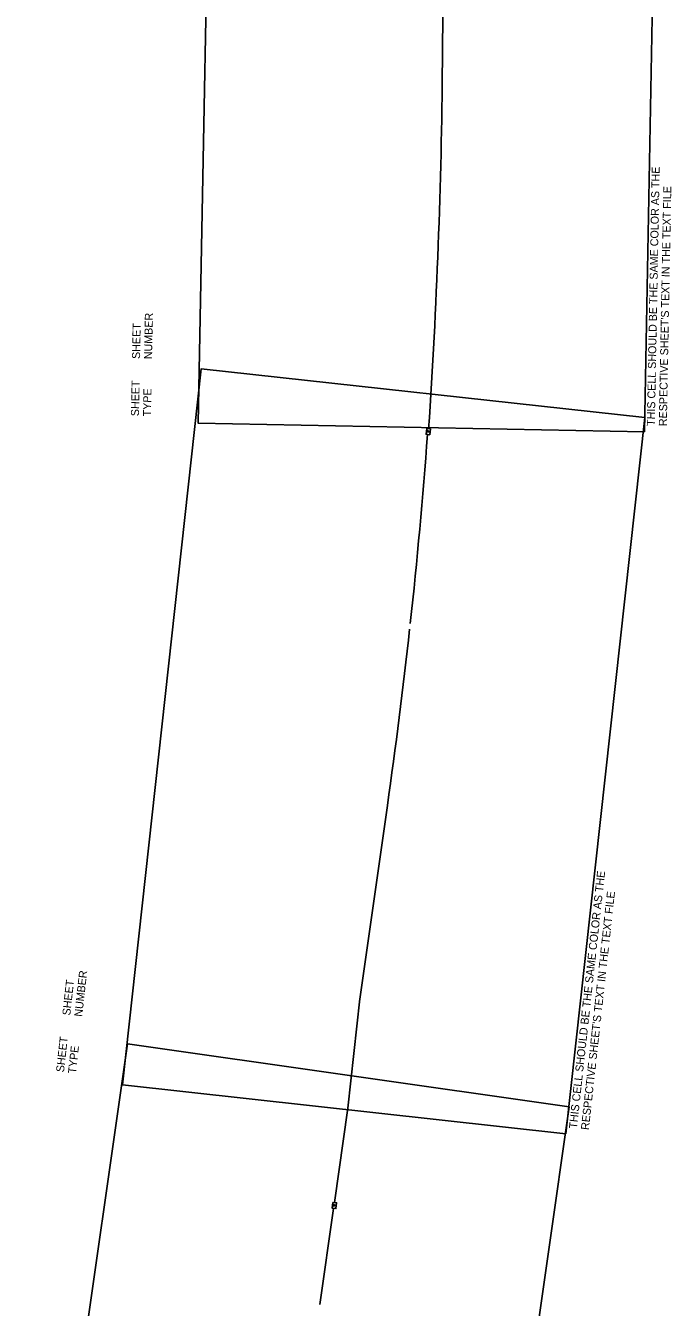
# Model space of a CAD drawing. Extents: x 601462 to 605493, y 331960 to 402715.
# Drawn here: x 602372 to 603783, y 367723 to 370525 of the extents above; entities that cross this region are included whole.
import ezdxf

# ---------------------------------------------------------------- set-up
doc = ezdxf.new("R2010")
doc.units = 0
for name, color, linetype in [('P_FTMS', 7, 'Continuous'), ('P_FTMSConduit', 7, 'Continuous'), ('P_MISC_TXT_1A (Construction)', 7, 'Continuous'), ('P_MISC_TXT_1B (Construction)', 7, 'Continuous')]:
    doc.layers.add(name, color=color, linetype=linetype)

# ---------------------------------------------------------------- blocks, each defined once
blk = doc.blocks.new('FTMS_FCV')
at = {"layer": 'P_FTMS'}
blk.add_line((13, 16), (1, -22), dxfattribs=at)
blk.add_lwpolyline([(39, 24), (-39, 24), (-39, -24), (39, -24)], close=True, dxfattribs=at)
blk.add_lwpolyline([(-12, 16), (1, -22)], dxfattribs=at)

msp = doc.modelspace()

# ---------------------------------------------------------------- linework, layer by layer
at = {"layer": 'P_FTMSConduit'}
for p, q in [((603076.4, 368158.5), (603102.3, 368397.2)), ((603047.1, 367952.1), (603076.3, 368158.3)), ((603015.2, 367729.4), (603045.1, 367939.4))]:
    msp.add_line(p, q, dxfattribs=at)
for points in [[(603282.9, 370445.5), (603284.6, 370696.6)], [(603102.2, 368396.7), (603162.6, 368820.1)]]:
    msp.add_lwpolyline(points, dxfattribs=at)
for centre, radius, start, end in [((589769.8, 370553.9), 13513.5, 356.13596, 359.54006), ((591099.1, 370531.4), 12184.5, 353.81235, 355.76292), ((591225.7, 370520.8), 12057.4, 351.89148, 353.73687)]:
    msp.add_arc(centre, radius, start, end, dxfattribs=at)
at = {"layer": 'P_MISC_TXT_1A (Construction)'}
for points in [[(603724.1, 369637.1), (603753.9, 371211.8), (602779.1, 371230.3), (602749.3, 369655.6)], [(603337.3, 366602.3), (603559.7, 368161.5), (602594.5, 368299.2), (602372.1, 366740)]]:
    msp.add_lwpolyline(points, close=True, dxfattribs=at)
at = {"layer": 'P_MISC_TXT_1B (Construction)'}
msp.add_lwpolyline([(603552.7, 368102.6), (603725, 369668.1), (602755.8, 369774.8), (602583.5, 368209.2)], close=True, dxfattribs=at)

# ---------------------------------------------------------------- block references
at = {"layer": 'P_FTMS', "xscale": 0.16404166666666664, "yscale": 0.16404166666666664, "rotation": 83.087993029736}
for p in [(603251.9, 369637.5), (603046.8, 367945.7)]:
    msp.add_blockref('FTMS_FCV', p, dxfattribs=at)

# ---------------------------------------------------------------- texts
at = {"layer": 'P_MISC_TXT_1A (Construction)'}
for s, p in [('THIS CELL SHOULD BE THE SAME COLOR AS THE', (603747, 369649.7)), ("RESPECTIVE SHEET'S TEXT IN THE TEXT FILE", (603773.2, 369649.2)), ('NUMBER', (602648.3, 369795.5)), ('SHEET', (602622, 369796)), ('SHEET', (602619.7, 369671)), ('TYPE', (602645.9, 369670.5))]:
    msp.add_text(s, height=17.5, rotation=88.9155, dxfattribs=at).set_placement(p)
at = {"layer": 'P_MISC_TXT_1B (Construction)'}
for s, p in [('THIS CELL SHOULD BE THE SAME COLOR AS THE', (603576.6, 368113)), ("RESPECTIVE SHEET'S TEXT IN THE TEXT FILE", (603602.7, 368110.1)), ('SHEET', (602469.5, 368360.6)), ('NUMBER', (602495.6, 368357.7)), ('SHEET', (602455.8, 368236.3)), ('TYPE', (602481.9, 368233.4))]:
    msp.add_text(s, height=17.5, rotation=83.7201, dxfattribs=at).set_placement(p)

doc.saveas('drawing.dxf')
